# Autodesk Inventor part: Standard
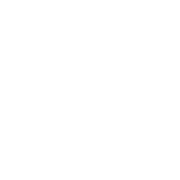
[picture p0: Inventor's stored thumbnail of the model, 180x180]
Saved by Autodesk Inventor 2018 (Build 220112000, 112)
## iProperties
Created: 2005-05
Part Number: Standard
Document SubType Name: Modeling
Designer: JWe
Density: 1 g/cm^3
Material: Generic
Appearance: Default
Author: JWe
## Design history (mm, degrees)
